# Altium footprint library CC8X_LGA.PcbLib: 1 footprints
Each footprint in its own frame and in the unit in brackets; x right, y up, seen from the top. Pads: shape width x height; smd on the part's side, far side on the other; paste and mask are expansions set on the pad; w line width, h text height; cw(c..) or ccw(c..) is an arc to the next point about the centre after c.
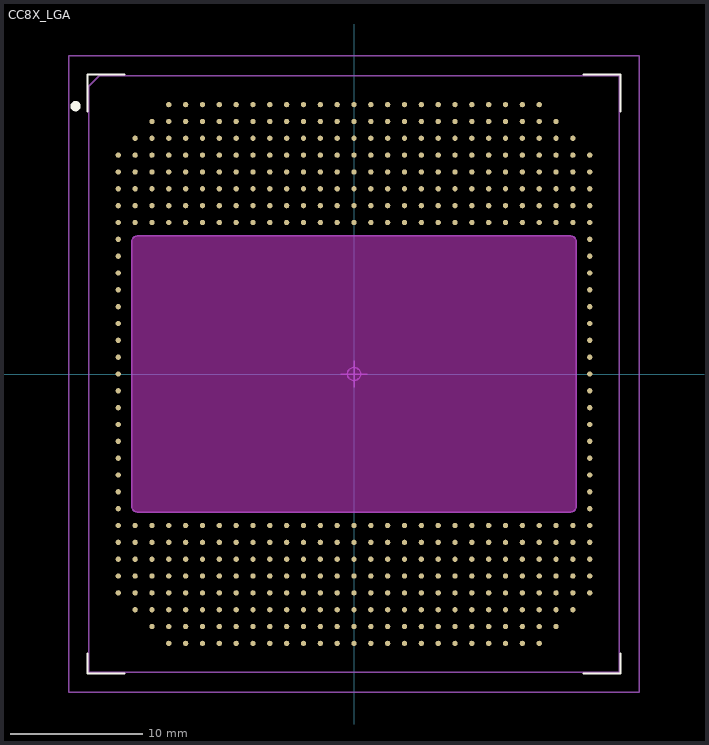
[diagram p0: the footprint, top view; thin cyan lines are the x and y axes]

## CC8X_LGA [mm]
height 5
pads (474):
  round 0.4 smd mask+0.05: A4(-13.97,20.32) A5(-12.7,20.32) A6(-11.43,20.32) A7(-10.16,20.32) A8(-8.89,20.32) A9(-7.62,20.32) A10(-6.35,20.32) A11(-5.08,20.32) A12(-3.81,20.32) A13(-2.54,20.32) A14(-1.27,20.32) A15(0,20.32) A16(1.27,20.32) A17(2.54,20.32) A18(3.81,20.32) A19(5.08,20.32) A20(6.35,20.32) A21(7.62,20.32) A22(8.89,20.32) A23(10.16,20.32) A24(11.43,20.32) A25(12.7,20.32) A26(13.97,20.32) AA1(-17.78,-5.08) AA29(17.78,-5.08) AB1(-17.78,-6.35) AB29(17.78,-6.35) AC1(-17.78,-7.62) AC29(17.78,-7.62) AD1(-17.78,-8.89) AD29(17.78,-8.89) AE1(-17.78,-10.16) AE29(17.78,-10.16) AF1(-17.78,-11.43) AF2(-16.51,-11.43) AF3(-15.24,-11.43) AF4(-13.97,-11.43) AF5(-12.7,-11.43) AF6(-11.43,-11.43) AF7(-10.16,-11.43) AF8(-8.89,-11.43) AF9(-7.62,-11.43) AF10(-6.35,-11.43) AF11(-5.08,-11.43) AF12(-3.81,-11.43) AF13(-2.54,-11.43) AF14(-1.27,-11.43) AF15(0,-11.43) AF16(1.27,-11.43) AF17(2.54,-11.43) AF18(3.81,-11.43) AF19(5.08,-11.43) AF20(6.35,-11.43) AF21(7.62,-11.43) AF22(8.89,-11.43) AF23(10.16,-11.43) AF24(11.43,-11.43) AF25(12.7,-11.43) AF26(13.97,-11.43) AF27(15.24,-11.43) AF28(16.51,-11.43) AF29(17.78,-11.43) AG1(-17.78,-12.7) AG2(-16.51,-12.7) AG3(-15.24,-12.7) AG4(-13.97,-12.7) AG5(-12.7,-12.7) AG6(-11.43,-12.7) AG7(-10.16,-12.7) AG8(-8.89,-12.7) AG9(-7.62,-12.7) AG10(-6.35,-12.7) AG11(-5.08,-12.7) AG12(-3.81,-12.7) AG13(-2.54,-12.7) AG14(-1.27,-12.7) AG15(0,-12.7) AG16(1.27,-12.7) AG17(2.54,-12.7) AG18(3.81,-12.7) AG19(5.08,-12.7) AG20(6.35,-12.7) AG21(7.62,-12.7) AG22(8.89,-12.7) AG23(10.16,-12.7) AG24(11.43,-12.7) AG25(12.7,-12.7) AG26(13.97,-12.7) AG27(15.24,-12.7) AG28(16.51,-12.7) AG29(17.78,-12.7) AH1(-17.78,-13.97) AH2(-16.51,-13.97) AH3(-15.24,-13.97) AH4(-13.97,-13.97) AH5(-12.7,-13.97) AH6(-11.43,-13.97) AH7(-10.16,-13.97) AH8(-8.89,-13.97) AH9(-7.62,-13.97) AH10(-6.35,-13.97) AH11(-5.08,-13.97) AH12(-3.81,-13.97) AH13(-2.54,-13.97) AH14(-1.27,-13.97) AH15(0,-13.97) AH16(1.27,-13.97) AH17(2.54,-13.97) AH18(3.81,-13.97) AH19(5.08,-13.97) AH20(6.35,-13.97) AH21(7.62,-13.97) AH22(8.89,-13.97) AH23(10.16,-13.97) AH24(11.43,-13.97) AH25(12.7,-13.97) AH26(13.97,-13.97) AH27(15.24,-13.97) AH28(16.51,-13.97) AH29(17.78,-13.97) AJ1(-17.78,-15.24) AJ2(-16.51,-15.24) AJ3(-15.24,-15.24) AJ4(-13.97,-15.24) AJ5(-12.7,-15.24) AJ6(-11.43,-15.24) AJ7(-10.16,-15.24) AJ8(-8.89,-15.24) AJ9(-7.62,-15.24) AJ10(-6.35,-15.24) AJ11(-5.08,-15.24) AJ12(-3.81,-15.24) AJ13(-2.54,-15.24) AJ14(-1.27,-15.24) AJ15(0,-15.24) AJ16(1.27,-15.24) AJ17(2.54,-15.24) AJ18(3.81,-15.24) AJ19(5.08,-15.24) AJ20(6.35,-15.24) AJ21(7.62,-15.24) AJ22(8.89,-15.24) AJ23(10.16,-15.24) AJ24(11.43,-15.24) AJ25(12.7,-15.24) AJ26(13.97,-15.24) AJ27(15.24,-15.24) AJ28(16.51,-15.24) AJ29(17.78,-15.24) AK1(-17.78,-16.51) AK2(-16.51,-16.51) AK3(-15.24,-16.51) AK4(-13.97,-16.51) AK5(-12.7,-16.51) AK6(-11.43,-16.51) AK7(-10.16,-16.51) AK8(-8.89,-16.51) AK9(-7.62,-16.51) AK10(-6.35,-16.51) AK11(-5.08,-16.51) AK12(-3.81,-16.51) AK13(-2.54,-16.51) AK14(-1.27,-16.51) AK15(0,-16.51) AK16(1.27,-16.51) AK17(2.54,-16.51) AK18(3.81,-16.51) AK19(5.08,-16.51) AK20(6.35,-16.51) AK21(7.62,-16.51) AK22(8.89,-16.51) AK23(10.16,-16.51) AK24(11.43,-16.51) AK25(12.7,-16.51) AK26(13.97,-16.51) AK27(15.24,-16.51) AK28(16.51,-16.51) AK29(17.78,-16.51) AL2(-16.51,-17.78) AL3(-15.24,-17.78) AL4(-13.97,-17.78) AL5(-12.7,-17.78) AL6(-11.43,-17.78) AL7(-10.16,-17.78) AL8(-8.89,-17.78) AL9(-7.62,-17.78) AL10(-6.35,-17.78) AL11(-5.08,-17.78) AL12(-3.81,-17.78) AL13(-2.54,-17.78) AL14(-1.27,-17.78) AL15(0,-17.78) AL16(1.27,-17.78) AL17(2.54,-17.78) AL18(3.81,-17.78) AL19(5.08,-17.78) AL20(6.35,-17.78) AL21(7.62,-17.78) AL22(8.89,-17.78) AL23(10.16,-17.78) AL24(11.43,-17.78) AL25(12.7,-17.78) AL26(13.97,-17.78) AL27(15.24,-17.78) AL28(16.51,-17.78) AM3(-15.24,-19.05) AM4(-13.97,-19.05) AM5(-12.7,-19.05) AM6(-11.43,-19.05) AM7(-10.16,-19.05) AM8(-8.89,-19.05) AM9(-7.62,-19.05) AM10(-6.35,-19.05) AM11(-5.08,-19.05) AM12(-3.81,-19.05) AM13(-2.54,-19.05) AM14(-1.27,-19.05) AM15(0,-19.05) AM16(1.27,-19.05) AM17(2.54,-19.05) AM18(3.81,-19.05) AM19(5.08,-19.05) AM20(6.35,-19.05) AM21(7.62,-19.05) AM22(8.89,-19.05) AM23(10.16,-19.05) AM24(11.43,-19.05) AM25(12.7,-19.05) AM26(13.97,-19.05) AM27(15.24,-19.05) AN4(-13.97,-20.32) AN5(-12.7,-20.32) AN6(-11.43,-20.32) AN7(-10.16,-20.32) AN8(-8.89,-20.32) AN9(-7.62,-20.32) AN10(-6.35,-20.32) AN11(-5.08,-20.32) AN12(-3.81,-20.32) AN13(-2.54,-20.32) AN14(-1.27,-20.32) AN15(0,-20.32) AN16(1.27,-20.32) AN17(2.54,-20.32) AN18(3.81,-20.32) AN19(5.08,-20.32) AN20(6.35,-20.32) AN21(7.62,-20.32) AN22(8.89,-20.32) AN23(10.16,-20.32) AN24(11.43,-20.32) AN25(12.7,-20.32) AN26(13.97,-20.32) B3(-15.24,19.05) B4(-13.97,19.05) B5(-12.7,19.05) B6(-11.43,19.05) B7(-10.16,19.05) B8(-8.89,19.05) B9(-7.62,19.05) B10(-6.35,19.05) B11(-5.08,19.05) B12(-3.81,19.05) B13(-2.54,19.05) B14(-1.27,19.05) B15(0,19.05) B16(1.27,19.05) B17(2.54,19.05) B18(3.81,19.05) B19(5.08,19.05) B20(6.35,19.05) B21(7.62,19.05) B22(8.89,19.05) B23(10.16,19.05) B24(11.43,19.05) B25(12.7,19.05) B26(13.97,19.05) B27(15.24,19.05) C2(-16.51,17.78) C3(-15.24,17.78) C4(-13.97,17.78) C5(-12.7,17.78) C6(-11.43,17.78) C7(-10.16,17.78) C8(-8.89,17.78) C9(-7.62,17.78) C10(-6.35,17.78) C11(-5.08,17.78) C12(-3.81,17.78) C13(-2.54,17.78) C14(-1.27,17.78) C15(0,17.78) C16(1.27,17.78) C17(2.54,17.78) C18(3.81,17.78) C19(5.08,17.78) C20(6.35,17.78) C21(7.62,17.78) C22(8.89,17.78) C23(10.16,17.78) C24(11.43,17.78) C25(12.7,17.78) C26(13.97,17.78) C27(15.24,17.78) C28(16.51,17.78) D1(-17.78,16.51) D2(-16.51,16.51) D3(-15.24,16.51) D4(-13.97,16.51) D5(-12.7,16.51) D6(-11.43,16.51) D7(-10.16,16.51) D8(-8.89,16.51) D9(-7.62,16.51) D10(-6.35,16.51) D11(-5.08,16.51) D12(-3.81,16.51) D13(-2.54,16.51) D14(-1.27,16.51) D15(0,16.51) D16(1.27,16.51) D17(2.54,16.51) D18(3.81,16.51) D19(5.08,16.51) D20(6.35,16.51) D21(7.62,16.51) D22(8.89,16.51) D23(10.16,16.51) D24(11.43,16.51) D25(12.7,16.51) D26(13.97,16.51) D27(15.24,16.51) D28(16.51,16.51) D29(17.78,16.51) E1(-17.78,15.24) E2(-16.51,15.24) E3(-15.24,15.24) E4(-13.97,15.24) E5(-12.7,15.24) E6(-11.43,15.24) E7(-10.16,15.24) E8(-8.89,15.24) E9(-7.62,15.24) E10(-6.35,15.24) E11(-5.08,15.24) E12(-3.81,15.24) E13(-2.54,15.24) E14(-1.27,15.24) E15(0,15.24) E16(1.27,15.24) E17(2.54,15.24) E18(3.81,15.24) E19(5.08,15.24) E20(6.35,15.24) E21(7.62,15.24) E22(8.89,15.24) E23(10.16,15.24) E24(11.43,15.24) E25(12.7,15.24) E26(13.97,15.24) E27(15.24,15.24) E28(16.51,15.24) E29(17.78,15.24) F1(-17.78,13.97) F2(-16.51,13.97) F3(-15.24,13.97) F4(-13.97,13.97) F5(-12.7,13.97) F6(-11.43,13.97) F7(-10.16,13.97) F8(-8.89,13.97) F9(-7.62,13.97) F10(-6.35,13.97) F11(-5.08,13.97) F12(-3.81,13.97) F13(-2.54,13.97) F14(-1.27,13.97) F15(0,13.97) F16(1.27,13.97) F17(2.54,13.97) F18(3.81,13.97) F19(5.08,13.97) F20(6.35,13.97) F21(7.62,13.97) F22(8.89,13.97) F23(10.16,13.97) F24(11.43,13.97) F25(12.7,13.97) F26(13.97,13.97) F27(15.24,13.97) F28(16.51,13.97) F29(17.78,13.97) G1(-17.78,12.7) G2(-16.51,12.7) G3(-15.24,12.7) G4(-13.97,12.7) G5(-12.7,12.7) G6(-11.43,12.7) G7(-10.16,12.7) G8(-8.89,12.7) G9(-7.62,12.7) G10(-6.35,12.7) G11(-5.08,12.7) G12(-3.81,12.7) G13(-2.54,12.7) G14(-1.27,12.7) G15(0,12.7) G16(1.27,12.7) G17(2.54,12.7) G18(3.81,12.7) G19(5.08,12.7) G20(6.35,12.7) G21(7.62,12.7) G22(8.89,12.7) G23(10.16,12.7) G24(11.43,12.7) G25(12.7,12.7) G26(13.97,12.7) G27(15.24,12.7) G28(16.51,12.7) G29(17.78,12.7) H1(-17.78,11.43) H2(-16.51,11.43) H3(-15.24,11.43) H4(-13.97,11.43) H5(-12.7,11.43) H6(-11.43,11.43) H7(-10.16,11.43) H8(-8.89,11.43) H9(-7.62,11.43) H10(-6.35,11.43) H11(-5.08,11.43) H12(-3.81,11.43) H13(-2.54,11.43) H14(-1.27,11.43) H15(0,11.43) H16(1.27,11.43) H17(2.54,11.43) H18(3.81,11.43) H19(5.08,11.43) H20(6.35,11.43) H21(7.62,11.43) H22(8.89,11.43) H23(10.16,11.43) H24(11.43,11.43) H25(12.7,11.43) H26(13.97,11.43) H27(15.24,11.43) H28(16.51,11.43) H29(17.78,11.43) J1(-17.78,10.16) J29(17.78,10.16) K1(-17.78,8.89) K29(17.78,8.89) L1(-17.78,7.62) L29(17.78,7.62) M1(-17.78,6.35) M29(17.78,6.35) N1(-17.78,5.08) N29(17.78,5.08) P1(-17.78,3.81) P29(17.78,3.81) R1(-17.78,2.54) R29(17.78,2.54) T1(-17.78,1.27) T29(17.78,1.27) U1(-17.78,0) U29(17.78,0) V1(-17.78,-1.27) V29(17.78,-1.27) W1(-17.78,-2.54) W29(17.78,-2.54) Y1(-17.78,-3.81) Y29(17.78,-3.81)
Top Overlay:
  circle w0.4: c-21,20.2 r0.182
  lines w0.15: -20.1,-21.1 -20.1,-22.6 -17.3,-22.6 ; -20.1,19.8 -20.1,22.6 -17.3,22.6 ; 17.3,-22.6 20.1,-22.6 20.1,-21.1 ; 17.3,22.6 20.1,22.6 20.1,19.8
Keep-Out Layer:
  board cut-out: 16.78,9.93 16.78,10.029 16.704,10.213 16.563,10.354 16.379,10.43 16.28,10.43 -16.28,10.43 -16.379,10.43 -16.563,10.354 -16.704,10.213 -16.78,10.029 -16.78,9.93 -16.78,-9.93 -16.78,-10.029 -16.704,-10.213 -16.563,-10.354 -16.379,-10.43 -16.28,-10.43 16.28,-10.43 16.379,-10.43 16.563,-10.354 16.704,-10.213 16.78,-10.029 16.78,-9.93
Mechanical 1:
  lines w0.1: -16.78,-9.93 ccw(c-16.28,-9.93) -16.28,-10.43 16.28,-10.43 ccw(c16.28,-9.93) 16.78,-9.93 16.78,9.93 ccw(c16.28,9.93) 16.28,10.43 -16.28,10.43 ccw(c-16.28,9.93) -16.78,9.93 -16.78,-9.93
Mechanical 3:
  lines w0.102: -20,-22.5 -20,21.7 -19.2,22.5 20,22.5 20,-22.5 -20,-22.5
  text ".Designator" at -1.25,-0.5 h1.02
Mechanical 20:
  circle w0.1: c0,0 r0.5
  lines w0.1: -1,0 1,0 ; 0,-1 0,1 ; -21.5,-24 21.5,-24 21.5,24 -21.5,24 -21.5,-24
3D body "30015412-01_A_CC8X_with_shield_w_pads_01.STEP": height 5.35, standoff -0.9, extent -20,-22.5 20,22.5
